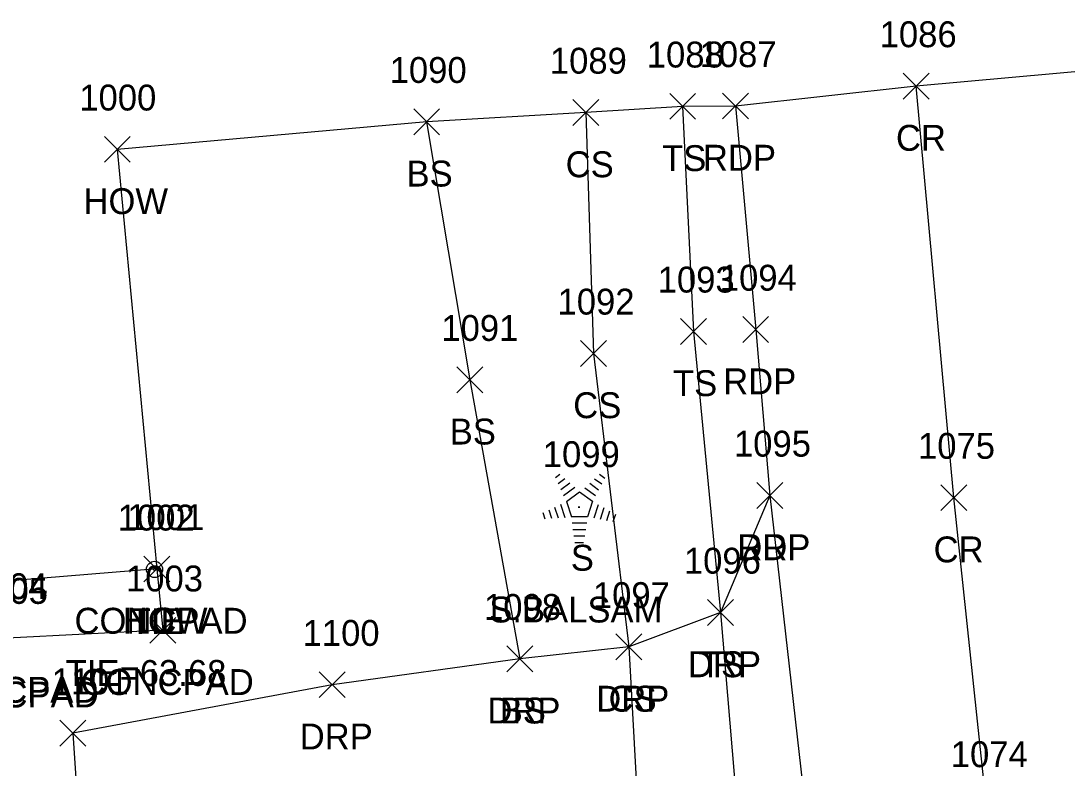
# Model space of a CAD drawing. Extents: x 1512665 to 1513714, y 110636 to 112816.
# Drawn here: x 1513126.6 to 1513207.4, y 111080.2 to 111137.9 of the extents above; entities that cross this region are included whole.
import ezdxf

# ---------------------------------------------------------------- set-up
doc = ezdxf.new("R2010")
doc.units = 0
for name, color, linetype in [('C_A', 7, 'Continuous'), ('C_C', 7, 'Continuous'), ('C_I', 7, 'Continuous'), ('CBP', 7, 'Continuous'), ('L_A', 7, 'Continuous'), ('L_C', 7, 'Continuous'), ('L_I', 7, 'Continuous'), ('L_TIC', 7, 'Continuous'), ('LBC', 7, 'Continuous'), ('LELB', 7, 'Continuous'), ('LS', 7, 'Continuous'), ('LSOGP', 7, 'Continuous'), ('LTC', 7, 'Continuous'), ('P_A', 7, 'Continuous'), ('P_I', 7, 'Continuous'), ('P_TIC', 7, 'Continuous'), ('PET', 7, 'Continuous'), ('PRC', 7, 'Continuous'), ('R_A', 7, 'Continuous'), ('R_I', 7, 'Continuous'), ('R_TIC', 7, 'Continuous'), ('RDP', 7, 'Continuous')]:
    doc.layers.add(name, color=color, linetype=linetype)

msp = doc.modelspace()

# ---------------------------------------------------------------- linework, layer by layer
at = {"layer": 'CBP'}
for radius in [0.625, 0.0833]:
    msp.add_circle((1513136.895, 111095.525), radius, dxfattribs=at)
at = {"layer": 'L_TIC'}
for points in [[(1513176.696, 111130.29), (1513178.696, 111132.29)], [(1513178.696, 111130.29), (1513176.696, 111132.29)], [(1513156.918, 111129.099), (1513158.918, 111131.099)], [(1513158.918, 111129.099), (1513156.918, 111131.099)], [(1513169.214, 111129.816), (1513171.214, 111131.816)], [(1513171.214, 111129.816), (1513169.214, 111131.816)], [(1513133.018, 111126.969), (1513135.018, 111128.969)], [(1513135.018, 111126.969), (1513133.018, 111128.969)], [(1513177.538, 111112.909), (1513179.538, 111114.909)], [(1513179.538, 111112.909), (1513177.538, 111114.909)], [(1513169.8, 111111.207), (1513171.8, 111113.207)], [(1513171.8, 111111.207), (1513169.8, 111113.207)], [(1513160.258, 111109.173), (1513162.258, 111111.173)], [(1513162.258, 111109.173), (1513160.258, 111111.173)], [(1513136.065, 111094.56), (1513138.065, 111096.56)], [(1513138.065, 111094.56), (1513136.065, 111096.56)], [(1513136.065, 111094.56), (1513138.065, 111096.56)], [(1513138.065, 111094.56), (1513136.065, 111096.56)], [(1513179.617, 111091.198), (1513181.617, 111093.198)], [(1513181.617, 111091.198), (1513179.617, 111093.198)], [(1513136.538, 111089.823), (1513138.538, 111091.823)], [(1513138.538, 111089.823), (1513136.538, 111091.823)], [(1513172.531, 111088.539), (1513174.531, 111090.539)], [(1513174.531, 111088.539), (1513172.531, 111090.539)], [(1513164.119, 111087.624), (1513166.119, 111089.624)], [(1513166.119, 111087.624), (1513164.119, 111089.624)]]:
    msp.add_lwpolyline(points, dxfattribs=at)
at = {"layer": 'LBC'}
msp.add_lwpolyline([(1513134.018, 111127.969), (1513137.065, 111095.56), (1513112.577, 111093.568)], dxfattribs=at)
at = {"layer": 'LELB'}
for points in [[(1513177.696, 111131.29), (1513178.538, 111113.909), (1513180.617, 111092.198), (1513182.065, 111075.11), (1513189.147, 111039.495), (1513191.756, 111010.28), (1513193.885, 111000.55), (1513190.646, 110994.729)], [(1513170.214, 111130.816), (1513170.8, 111112.207), (1513173.531, 111089.539), (1513174.355, 111074.616), (1513179.798, 111058.724), (1513184.877, 111038.844), (1513186.524, 111012.71), (1513182.7, 110990.922), (1513167.492, 110986.513), (1513158.395, 110982.164)], [(1513157.918, 111130.099), (1513161.258, 111110.173), (1513165.119, 111088.624)]]:
    msp.add_lwpolyline(points, dxfattribs=at)
at = {"layer": 'LS'}
msp.add_lwpolyline([(1513137.065, 111095.56), (1513137.538, 111090.823), (1513125.533, 111090.227), (1513125.564, 111089.864), (1513112.991, 111089.01), (1513112.577, 111093.568)], dxfattribs=at)
at = {"layer": 'LSOGP'}
msp.add_lwpolyline([(1513210.299, 111134.171), (1513195.743, 111132.859), (1513181.776, 111131.317), (1513177.696, 111131.291), (1513170.215, 111130.814), (1513157.919, 111130.097), (1513134.018, 111127.969), (1513137.063, 111095.561), (1513112.579, 111093.567), (1513104.258, 111092.854), (1513090.883, 111093.435), (1513081.722, 111090.573), (1513074.288, 111090.882), (1513064.744, 111092.42), (1513057.55, 111092.594), (1513050.575, 111091.964), (1513042.76, 111092.546)], dxfattribs=at)
at = {"layer": 'LTC'}
for p, q in [((1513167.864, 111102.633), (1513168.218, 111102.89)), ((1513171.262, 111102.873), (1513171.681, 111102.569)), ((1513168.073, 111102.167), (1513168.603, 111102.552)), ((1513168.283, 111101.702), (1513168.987, 111102.213)), ((1513170.52, 111102.177), (1513171.199, 111101.683)), ((1513170.891, 111102.525), (1513171.441, 111102.126)), ((1513168.493, 111101.236), (1513169.371, 111101.874)), ((1513168.717, 111100.781), (1513169.729, 111101.515)), ((1513169.729, 111101.515), (1513170.726, 111100.79)), ((1513170.149, 111101.828), (1513170.958, 111101.24)), ((1513167.807, 111100.345), (1513168.078, 111099.51)), ((1513168.263, 111100.562), (1513168.593, 111099.542)), ((1513168.717, 111100.781), (1513169.104, 111099.587)), ((1513170.726, 111100.79), (1513170.335, 111099.587)), ((1513171.163, 111100.52), (1513170.826, 111099.48)), ((1513166.896, 111099.912), (1513167.048, 111099.444)), ((1513167.352, 111100.129), (1513167.563, 111099.477)), ((1513170.335, 111099.587), (1513169.104, 111099.587)), ((1513171.608, 111100.269), (1513171.321, 111099.385)), ((1513172.053, 111100.019), (1513171.816, 111099.29)), ((1513172.497, 111099.769), (1513172.31, 111099.195)), ((1513170.296, 111099.087), (1513169.152, 111099.087)), ((1513170.213, 111098.587), (1513169.224, 111098.587)), ((1513170.129, 111098.087), (1513169.297, 111098.087)), ((1513170.045, 111097.587), (1513169.37, 111097.587))]:
    msp.add_line(p, q, dxfattribs=at)
at = {"layer": 'P_TIC'}
for points in [[(1513194.743, 111131.859), (1513196.743, 111133.859)], [(1513196.743, 111131.859), (1513194.743, 111133.859)], [(1513180.776, 111130.319), (1513182.776, 111132.319)], [(1513182.776, 111130.319), (1513180.776, 111132.319)], [(1513182.338, 111113.054), (1513184.338, 111115.054)], [(1513184.338, 111113.054), (1513182.338, 111115.054)], [(1513183.43, 111100.236), (1513185.43, 111102.236)], [(1513185.43, 111100.236), (1513183.43, 111102.236)], [(1513197.65, 111100.069), (1513199.65, 111102.069)], [(1513199.65, 111100.069), (1513197.65, 111102.069)]]:
    msp.add_lwpolyline(points, dxfattribs=at)
at = {"layer": 'PET'}
msp.add_lwpolyline([(1513181.776, 111131.319), (1513183.338, 111114.054), (1513184.43, 111101.236), (1513188.028, 111069.406), (1513191.639, 111039.849), (1513195.641, 111010.584), (1513196.783, 111002.78), (1513199.52, 110982.675), (1513202.263, 110966.835), (1513206.801, 110942.098), (1513212.833, 110910.789), (1513216.968, 110890.917), (1513223.708, 110861.112), (1513236.039, 110809.069), (1513241.458, 110788.527), (1513249.294, 110760.242)], dxfattribs=at)
at = {"layer": 'PRC'}
msp.add_lwpolyline([(1513262.692, 110765.317), (1513252.951, 110800.58), (1513242.765, 110841.606), (1513231.954, 110888.448), (1513222.372, 110936.123), (1513216.373, 110968.756), (1513211.795, 110996.68), (1513206.033, 111035.98), (1513201.182, 111077.251), (1513198.65, 111101.069), (1513195.743, 111132.859)], dxfattribs=at)
at = {"layer": 'R_TIC'}
for points in [[(1513183.43, 111100.236), (1513185.43, 111102.236)], [(1513185.43, 111100.236), (1513183.43, 111102.236)], [(1513179.617, 111091.198), (1513181.617, 111093.198)], [(1513181.617, 111091.198), (1513179.617, 111093.198)], [(1513172.531, 111088.539), (1513174.531, 111090.539)], [(1513174.531, 111088.539), (1513172.531, 111090.539)], [(1513164.119, 111087.624), (1513166.119, 111089.624)], [(1513166.119, 111087.624), (1513164.119, 111089.624)], [(1513149.623, 111085.619), (1513151.623, 111087.619)], [(1513151.623, 111085.619), (1513149.623, 111087.619)], [(1513129.582, 111081.877), (1513131.582, 111083.877)], [(1513131.582, 111081.877), (1513129.582, 111083.877)]]:
    msp.add_lwpolyline(points, dxfattribs=at)
at = {"layer": 'RDP'}
msp.add_lwpolyline([(1513184.43, 111101.236), (1513180.617, 111092.198), (1513173.531, 111089.539), (1513165.119, 111088.624), (1513150.623, 111086.619), (1513130.582, 111082.877), (1513131.678, 111066.231), (1513135.641, 111052.21), (1513146.507, 111053.737), (1513148.477, 111054.17), (1513147.377, 111061.486), (1513152.471, 111070.911), (1513164.166, 111073.64), (1513174.355, 111074.616), (1513182.065, 111075.11), (1513188.028, 111069.406)], dxfattribs=at)

# ---------------------------------------------------------------- texts
at = {"layer": 'C_A'}
msp.add_text('TIE', height=2, dxfattribs=at).set_placement((1513134.974, 111090.525))
at = {"layer": 'C_C'}
msp.add_text('TIE=63.68', height=2, dxfattribs=at).set_placement((1513130.029, 111086.525))
at = {"layer": 'C_I'}
msp.add_text('1002', height=2, dxfattribs=at).set_placement((1513134.045, 111098.525))
at = {"layer": 'L_A'}
for s, p in [('CS', (1513168.655, 111125.816)), ('TS', (1513176.105, 111126.29)), ('BS', (1513156.359, 111125.099)), ('HOW', (1513131.404, 111122.969)), ('TS', (1513176.947, 111108.909)), ('CS', (1513169.241, 111107.207)), ('BS', (1513159.699, 111105.173)), ('S', (1513169.055, 111095.425)), ('CONCPAD', (1513130.71, 111090.56)), ('HOW', (1513134.45, 111090.56)), ('TS', (1513179.027, 111087.198)), ('CONCPAD', (1513131.184, 111085.823)), ('CONCPAD', (1513119.179, 111085.227)), ('CONCPAD', (1513119.209, 111084.864)), ('CS', (1513171.972, 111084.539)), ('BS', (1513163.56, 111083.624))]:
    msp.add_text(s, height=2, dxfattribs=at).set_placement(p)
at = {"layer": 'L_C'}
msp.add_text('S.BALSAM', height=2, dxfattribs=at).set_placement((1513162.755, 111091.425))
at = {"layer": 'L_I'}
for s, p in [('1088', (1513174.924, 111134.29)), ('1090', (1513155.06, 111133.099)), ('1089', (1513167.435, 111133.816)), ('1000', (1513131.081, 111130.969)), ('1093', (1513175.766, 111116.909)), ('1092', (1513168.028, 111115.207)), ('1091', (1513159.053, 111113.173)), ('1099', (1513166.889, 111103.425)), ('1001', (1513134.781, 111098.56)), ('1001', (1513134.781, 111098.56)), ('1096', (1513177.791, 111095.198)), ('1003', (1513134.688, 111093.823)), ('1004', (1513122.683, 111093.227)), ('1005', (1513122.713, 111092.864)), ('1097', (1513170.759, 111092.539)), ('1098', (1513162.347, 111091.624))]:
    msp.add_text(s, height=2, dxfattribs=at).set_placement(p)
at = {"layer": 'LTC'}
msp.add_text('.', height=1.037, rotation=270, dxfattribs=at).set_placement((1513169.611, 111100.529))
at = {"layer": 'P_A'}
for s, p in [('CR', (1513194.176, 111127.859)), ('RDP', (1513179.264, 111126.319)), ('RDP', (1513180.826, 111109.054)), ('RDP', (1513181.918, 111096.236)), ('CR', (1513197.083, 111096.069))]:
    msp.add_text(s, height=2, dxfattribs=at).set_placement(p)
at = {"layer": 'P_I'}
for s, p in [('1086', (1513192.916, 111135.859)), ('1087', (1513179.004, 111134.319)), ('1094', (1513180.566, 111117.054)), ('1095', (1513181.659, 111104.236)), ('1075', (1513195.878, 111104.069)), ('1074', (1513198.411, 111080.251))]:
    msp.add_text(s, height=2, dxfattribs=at).set_placement(p)
at = {"layer": 'R_A'}
for p in [(1513181.918, 111096.236), (1513178.106, 111087.198), (1513171.019, 111084.539), (1513162.607, 111083.624), (1513148.111, 111081.619)]:
    msp.add_text('DRP', height=2, dxfattribs=at).set_placement(p)
at = {"layer": 'R_I'}
for s, p in [('1095', (1513181.659, 111104.236)), ('1096', (1513177.791, 111095.198)), ('1097', (1513170.759, 111092.539)), ('1098', (1513162.347, 111091.624)), ('1100', (1513148.332, 111089.619)), ('1101', (1513128.944, 111085.877))]:
    msp.add_text(s, height=2, dxfattribs=at).set_placement(p)

doc.saveas('drawing.dxf')
